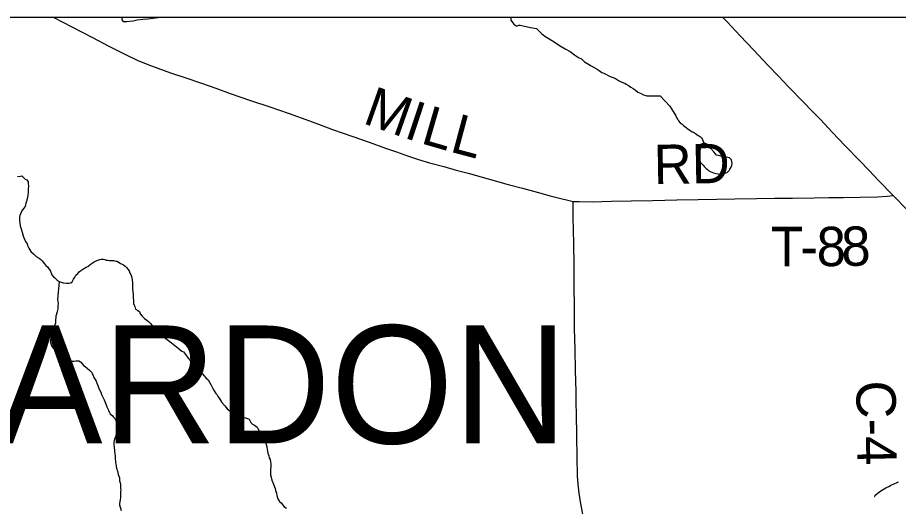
# Model space of a CAD drawing. Extents: x 103424 to 286016, y 38711 to 110967.
# Drawn here: x 127210 to 133964, y 107218 to 110967 of the extents above; entities that cross this region are included whole.
import ezdxf

# ---------------------------------------------------------------- set-up
doc = ezdxf.new("R2010")
doc.units = 0
for name, color, linetype in [('GM_X_Corporation', 7, 'Continuous'), ('GM_X_County_Road', 7, 'Continuous'), ('GM_X_County_Road_Text', 7, 'Continuous'), ('GM_X_Minor_Lake', 7, 'Continuous'), ('GM_X_Minor_River', 7, 'Continuous'), ('GM_X_Township_Road', 7, 'Continuous'), ('GM_X_Township_Road_Text', 7, 'Continuous'), ('GM_X_Township_Text', 7, 'Continuous')]:
    doc.layers.add(name, color=color, linetype=linetype)

msp = doc.modelspace()

# ---------------------------------------------------------------- linework, layer by layer
at = {"layer": 'GM_X_Corporation'}
msp.add_lwpolyline([(103423.7, 96534.8), (103423.7, 38711.2), (175679.7, 38711.2), (175679.7, 110967.2), (119699, 110967.2), (119716.9, 106542.5), (119719.8, 106322.8), (119720.8, 106006.3), (119709.7, 99445.7), (119706.4, 99064.2), (119663.9, 96690), (117026.4, 96688.2), (115542.1, 96665), (105081.7, 96574.5)], close=True, dxfattribs=at)
msp.add_lwpolyline([(148354.5, 110967.2), (119699, 110967.2), (119716.9, 106542.5), (119719.8, 106322.8), (119720.8, 106006.3), (119709.7, 99445.7), (119706.4, 99064.2), (119663.9, 96690), (127752.9, 96778.3), (127904.6, 96781), (127960.9, 96782.1), (128017.2, 96783.1), (128144.7, 96785.8), (131350.5, 96844.5), (131500.4, 96848.9), (132289.6, 96863.9), (132581, 96869.6), (132838, 96874.6), (133225.9, 96882.3), (133496.3, 96888.5), (133864.7, 96896.9), (134160.1, 96903.7)], dxfattribs=at)
at = {"layer": 'GM_X_County_Road'}
msp.add_lwpolyline([(132619.3, 110967.2), (132651.2, 110934.2), (132752, 110826.7), (132852.9, 110719.3), (132967, 110600), (133044.9, 110518.6), (133122.8, 110437.2), (133237.5, 110318.4), (133301.8, 110251.8), (133366.1, 110185.1), (133460.2, 110086.2), (133554.3, 109987.3), (133668.4, 109868), (133740.1, 109793.2), (133811.7, 109718.3), (133925, 109602.4), (134033.5, 109490.7), (134125.5, 109396)], dxfattribs=at)
at = {"layer": 'GM_X_Minor_Lake'}
msp.add_line((128248.7, 110963), (128288.1, 110967.2), dxfattribs=at)
for points in [[(128010.2, 110967.2), (128010.3, 110960.8), (128010.4, 110950.7), (128020.6, 110938.6), (128046.9, 110936.9), (128069.1, 110939.1), (128095.3, 110941.4), (128127.5, 110949.8), (128171.9, 110954.3), (128208.2, 110958.7), (128248.7, 110963)], [(132448, 109993.7), (132444.5, 109959.3), (132440.7, 109945.1), (132439, 109932.9), (132437.2, 109920.8), (132437.4, 109908.6), (132435.6, 109892.5), (132435.9, 109876.3), (132442.3, 109860.3), (132456.7, 109844.3), (132467, 109834.4), (132475.2, 109824.5), (132489.6, 109810.6), (132499.8, 109802.7), (132510.1, 109792.8), (132522.3, 109787), (132534.5, 109781.1), (132546.7, 109777.3), (132567, 109771.6), (132583.2, 109767.8), (132593.3, 109766), (132605.4, 109766.2), (132623.5, 109768.6), (132633.5, 109772.8), (132651.6, 109779.2), (132665.5, 109793.6), (132671.3, 109803.8), (132681.1, 109820.1), (132686.9, 109836.4), (132688.7, 109846.5), (132688.4, 109862.7), (132684.1, 109876.7), (132669.7, 109892.6), (132655.6, 109894.4), (132643.4, 109896.2), (132627.3, 109897.9), (132617.1, 109899.8), (132602.9, 109905.6), (132584.7, 109909.3), (132570.5, 109913.1), (132562.2, 109923), (132547.9, 109936.9), (132527.2, 109962.8), (132516.9, 109974.7), (132508.6, 109984.7), (132498.4, 109996.6), (132486.2, 110000.4), (132476.1, 110002.3), (132466, 110002.1), (132454, 109995.8), (132448, 109993.7)], [(132448, 109993.7), (132444.5, 109959.3), (132440.7, 109945.1), (132439, 109932.9), (132437.2, 109920.8), (132437.4, 109908.6), (132435.6, 109892.5), (132435.9, 109876.3), (132442.3, 109860.3), (132456.7, 109844.3), (132467, 109834.4), (132475.2, 109824.5), (132489.6, 109810.6), (132499.8, 109802.7), (132510.1, 109792.8), (132522.3, 109787), (132534.5, 109781.1), (132546.7, 109777.3), (132567, 109771.6), (132583.2, 109767.8), (132593.3, 109766), (132605.4, 109766.2), (132623.5, 109768.6), (132633.5, 109772.8), (132651.6, 109779.2), (132665.5, 109793.6)], [(132665.5, 109793.6), (132671.3, 109803.8), (132681.1, 109820.1), (132686.9, 109836.4), (132688.7, 109846.5), (132688.4, 109862.7), (132684.1, 109876.7), (132669.7, 109892.6), (132655.6, 109894.4), (132643.4, 109896.2), (132627.3, 109897.9), (132617.1, 109899.8), (132602.9, 109905.6), (132584.7, 109909.3), (132570.5, 109913.1), (132562.2, 109923), (132547.9, 109936.9), (132527.2, 109962.8), (132516.9, 109974.7), (132508.6, 109984.7), (132498.4, 109996.6), (132486.2, 110000.4), (132476.1, 110002.3), (132466, 110002.1), (132454, 109995.8), (132448, 109993.7)]]:
    msp.add_lwpolyline(points, dxfattribs=at)
at = {"layer": 'GM_X_Minor_River'}
for points in [[(130990, 110967.2), (130991.5, 110964.3), (130993.7, 110948.1), (131014.3, 110918), (131034.6, 110904.1), (131044.7, 110904.2), (131054.8, 110908.3), (131064.9, 110908.4), (131143.8, 110891), (131174.2, 110887.3), (131190.4, 110883.4), (131202.6, 110871.4), (131212.9, 110859.4), (131227.2, 110845.4), (131253.7, 110825.5), (131278.1, 110809.6), (131300.4, 110797.7), (131324.9, 110781.8), (131351.3, 110763.8), (131377.8, 110745.9), (131410.3, 110728.1), (131446.9, 110706.2), (131481.6, 110682.3), (131512.1, 110662.4), (131534.4, 110650.5), (131556.9, 110628.5), (131587.4, 110610.7), (131609.8, 110596.8), (131632.2, 110584.9), (131654.5, 110570.9), (131670.8, 110561), (131681, 110553), (131691.2, 110547.1), (131705.4, 110541.1), (131721.6, 110533.2), (131737.9, 110523.3), (131754.2, 110515.4), (131776.5, 110507.5), (131794.7, 110499.6), (131819.1, 110485.7), (131839.5, 110473.8), (131855.7, 110467.9), (131865.8, 110464), (131878, 110456), (131894.3, 110446.1), (131912.6, 110434.2), (131931, 110422.2), (131947.2, 110412.3), (131965.6, 110396.3), (131992, 110384.4), (132010.3, 110374.5), (132026.5, 110370.7), (132036.6, 110366.7), (132138.2, 110365.9)], [(132138.2, 110365.9), (132212.6, 110288.4), (132225.1, 110268.4), (132258.3, 110214.5), (132266.7, 110196.5), (132273, 110184.4), (132279.2, 110174.5), (132291.6, 110160.5), (132305.9, 110148.7), (132316.2, 110140.8), (132326.4, 110132.9), (132336.7, 110123), (132348.9, 110115.1), (132359.2, 110105.2), (132373.4, 110099.4), (132383.6, 110091.5), (132393.8, 110087.6), (132408.1, 110077.8), (132418.3, 110069.9), (132428.5, 110064), (132438.7, 110058.1), (132455.1, 110046.3), (132476.1, 110002.3)], [(127210.4, 109748.9), (127232.5, 109751.2), (127242.6, 109753.3), (127267.2, 109727.3), (127281.3, 109723.4), (127291.6, 109707.3), (127291.7, 109697.2), (127294.1, 109671), (127292.2, 109656.8), (127292.4, 109640.7), (127290.5, 109626.5), (127288.8, 109606.3), (127285, 109586.1), (127281.1, 109569.9), (127279.2, 109557.7), (127273.3, 109543.5), (127267.5, 109519.2), (127255.6, 109503), (127241.7, 109484.6), (127228, 109450.2), (127226.1, 109436), (127224.2, 109423.9), (127224.4, 109409.7), (127226.6, 109393.6), (127230.9, 109369.4), (127237.2, 109347.2), (127245.6, 109321.1), (127254, 109292.9), (127264.4, 109264.7), (127274.8, 109242.6), (127283, 109232.6), (127287.2, 109218.5), (127297.5, 109198.4), (127312, 109174.3), (127332.4, 109154.3), (127352.8, 109134.3), (127375.2, 109122.4), (127389.4, 109112.4), (127401.7, 109098.4), (127414, 109080.4), (127426.3, 109066.3), (127438.6, 109054.3), (127463.2, 109022.3), (127473.6, 108994.1), (127485.9, 108978.1), (127496.1, 108970.1), (127512.5, 108954.1), (127528.8, 108942.1), (127545, 108938.2), (127559.2, 108932.3), (127585.4, 108930.6), (127603.6, 108930.8), (127617.7, 108932.9), (127627.7, 108941.1), (127639.6, 108961.4), (127649.6, 108975.7), (127657.4, 108991.9)], [(127657.4, 108991.9), (127671.4, 109004.2), (127683.4, 109016.4), (127695.4, 109026.6), (127709.4, 109036.9), (127723.5, 109045.1), (127735.5, 109053.3), (127749.6, 109057.5), (127767.6, 109073.8), (127781.6, 109084), (127797.6, 109094.3), (127817.7, 109104.6), (127839.9, 109110.9), (127849.9, 109113), (127868.1, 109113.2), (127880.3, 109111.3), (127890.4, 109107.3), (127902.5, 109105.4), (127914.7, 109103.5), (127928.8, 109103.7), (127945, 109103.8), (127963.2, 109100), (127973.3, 109098.1), (127999.8, 109080.1), (128012, 109076.2), (128022.1, 109070.3), (128034.4, 109060.3), (128044.6, 109050.3), (128054.8, 109038.3), (128065.1, 109024.2), (128071.3, 109008.1), (128079.5, 108996.1), (128083.7, 108982), (128088.1, 108955.8), (128090.4, 108933.6), (128090.6, 108915.4), (128090.9, 108887.1), (128093.2, 108862.9), (128095.4, 108844.8), (128097.6, 108830.7), (128097.8, 108818.5), (128098, 108798.3), (128100.3, 108774.1), (128104.5, 108762), (128108.6, 108752), (128114.9, 108731.9), (128133.2, 108719.9), (128145.4, 108714), (128149.7, 108695.8), (128166.1, 108675.8), (128184.4, 108659.8), (128200.8, 108645.8), (128215, 108635.9), (128227.3, 108623.9), (128241.6, 108605.9), (128258, 108581.8), (128280.5, 108557.8), (128311.1, 108531.8), (128345.8, 108505.9), (128378.4, 108482), (128453.8, 108422.2), (128470.1, 108408.2), (128482.3, 108402.2), (128504.9, 108372.2), (128529.5, 108342.1), (128558.1, 108308.1), (128586.8, 108274), (128607.3, 108254), (128619.5, 108244), (128627.7, 108234), (128637.9, 108222), (128656.3, 108202), (128670.6, 108188), (128680.9, 108171.9), (128693.3, 108151.9), (128703.6, 108127.7), (128718.1, 108103.6), (128730.4, 108083.6), (128740.6, 108073.6), (128748.9, 108059.5), (128761.2, 108041.4), (128777.7, 108015.3), (128798.2, 107989.3), (128818.6, 107965.3), (128839, 107951.3), (128857.3, 107943.4), (128877.6, 107929.5), (128902.1, 107911.6), (128926.4, 107899.7), (128956.8, 107895.9), (128973, 107892.1), (128985.2, 107888.1), (128999.6, 107862), (129011.9, 107848), (129026.1, 107840.1), (129038.3, 107834.1), (129048.5, 107826.2), (129052.7, 107816.1), (129065, 107792), (129087.5, 107770), (129101.9, 107747.9)], [(127528.8, 108942.1), (127516.2, 108804.7), (127520.6, 108774.4), (127518.8, 108754.2), (127518.9, 108744.1), (127519, 108734), (127515.1, 108721.8), (127513.3, 108709.7), (127503.5, 108677.3), (127503.7, 108663.1), (127501.8, 108651), (127500, 108638.9), (127500.1, 108622.7), (127494.3, 108604.5), (127486.5, 108576.1), (127480.8, 108551.8), (127472.9, 108529.5), (127465.1, 108511.3), (127463.2, 108497.1), (127461.3, 108485), (127463.5, 108474.9), (127467.7, 108460.8), (127469.8, 108450.7), (127482.1, 108432.7), (127498.5, 108416.7), (127506.7, 108406.6), (127521, 108388.6), (127531.3, 108376.6), (127543.5, 108364.6), (127553.7, 108356.6), (127563.9, 108350.7), (127574.1, 108344.7), (127588.3, 108338.8), (127606.5, 108332.9), (127616.6, 108331), (127628.8, 108331.1), (127640.9, 108331.2), (127657, 108335.4), (127669.1, 108335.5), (127679.2, 108333.6), (127691.4, 108325.7), (127707.8, 108309.7), (127716, 108299.7), (127728.2, 108289.7), (127764.9, 108259.7), (127779.2, 108245.8), (127783.4, 108235.7), (127789.6, 108221.6), (127795.8, 108205.5), (127804.1, 108191.5), (127812.3, 108177.4), (127818.5, 108163.3), (127824.8, 108145.2), (127831.1, 108129.1), (127839.3, 108111), (127847.6, 108094.9), (127853.9, 108076.8), (127862.2, 108060.7), (127868.4, 108046.7), (127874.6, 108034.6), (127878.8, 108022.5), (127885, 108008.5), (127889.2, 107996.4), (127895.4, 107980.3), (127903.7, 107962.2), (127907.9, 107952.1), (127912, 107942.1), (127920.3, 107928), (127934.5, 107916), (127946.8, 107902), (127957, 107892), (127963.2, 107877.9), (127967.5, 107861.8), (127971.7, 107843.7), (127973.9, 107827.6), (127974.1, 107813.4), (127972.3, 107797.2), (127962.6, 107760.8), (127960.7, 107750.7), (127956.8, 107740.5), (127950.9, 107724.3), (127949, 107714.2), (127949.2, 107700.1), (127949.3, 107687.9), (127951.4, 107677.9), (127951.6, 107667.8), (127953.8, 107649.6), (127953.9, 107639.5), (127956.1, 107621.4), (127958.3, 107605.2), (127958.6, 107579), (127960.8, 107564.8), (127961, 107552.7), (127963.1, 107540.6), (127967.3, 107530.6), (127967.4, 107520.5), (127971.6, 107504.3), (127973.8, 107494.3), (127977.9, 107484.2), (127980.1, 107474.1), (127982.2, 107462)], [(129101.9, 107747.9), (129120.9, 107675.4), (129123.2, 107653.2), (129129.6, 107625), (129135.9, 107604.8), (129140.1, 107590.7), (129146.3, 107576.7), (129150.6, 107558.5), (129152.8, 107544.4), (129153, 107524.2), (129149.3, 107495.9), (129149.4, 107485.8), (129149.5, 107473.7), (129149.7, 107459.6), (129154, 107441.4), (129160.3, 107419.3), (129172.7, 107389.1), (129185.3, 107354.9), (129191.6, 107330.7), (129195.7, 107320.6), (129198, 107302.5), (129206.4, 107276.3), (129214.6, 107264.3), (129218.7, 107254.2), (129233, 107242.2), (129251.5, 107218.2), (129271.8, 107204.2)], [(127982.2, 107462), (127986.4, 107450), (127990.6, 107437.9), (127992.8, 107423.8), (127992.9, 107413.7), (127997.1, 107397.5), (127999.3, 107385.5), (127999.4, 107375.4), (127999.6, 107355.2), (128001.8, 107345.1), (127999.9, 107332.9), (128000.1, 107316.8), (127998.2, 107300.6), (127998.4, 107286.5), (127996.6, 107270.3), (127994.8, 107252.1), (127992.9, 107240), (127993, 107229.9), (128005.6, 107187.6)], [(133781.9, 107292.7), (133783.9, 107292.7), (133785.7, 107304.9), (133829.5, 107336), (133867.4, 107360.9), (133895.4, 107373.5), (133905.4, 107379.7), (133931.5, 107390.3), (133955.5, 107400.8), (133965.5, 107405.1)]]:
    msp.add_lwpolyline(points, dxfattribs=at)
at = {"layer": 'GM_X_Township_Road'}
for points in [[(127487.7, 110967.2), (127626.3, 110895.5), (127705.5, 110854.6), (127784.7, 110813.6), (127910.8, 110748.5), (128037, 110683.3), (128127.3, 110640.7), (128209.3, 110607.3), (128284.6, 110579.1), (128382.6, 110544.8), (128501, 110504.3), (128619.3, 110463.8), (128729.9, 110424.9), (128840.6, 110386), (128996.7, 110332.4), (129145, 110281.5), (129293.4, 110230.6), (129448.6, 110174.4), (129537.4, 110142.2), (129626.2, 110110), (129781.8, 110054.9), (129906.5, 110010.7), (130031.1, 109966.6), (130115.3, 109937.1), (130199.4, 109907.6), (130285.1, 109879.3), (130369.8, 109853.9), (130478.5, 109823.8), (130572.2, 109798.2), (130665.9, 109772.7), (130819.5, 109730.4), (130973.1, 109688.2), (131083.2, 109658), (131193.2, 109627.9), (131294.1, 109601), (131376, 109579.4), (131428.4, 109567), (131470.3, 109557.8), (131516.9, 109556.5), (131615.8, 109555.2), (131765.2, 109558.5), (131914.5, 109561.7), (132079.5, 109565.4), (132172.2, 109567.5), (132265, 109569.6), (132430, 109572), (132570.6, 109574.1), (132711.1, 109576.1), (132876.1, 109578.8), (133014.7, 109581.1), (133153.3, 109583.3), (133318.3, 109585.3), (133430.1, 109586.6), (133541.8, 109587.9), (133672.5, 109590.5), (133803.1, 109593.2), (133877.9, 109596.4), (133925, 109602.4)], [(131545.7, 107157.2), (131526.8, 107253.3), (131517, 107320), (131509.2, 107387.3), (131505, 107452.5), (131500.8, 107594.2), (131498, 107759.2), (131495.3, 107924.3), (131493.8, 108011), (131492.4, 108097.8), (131488.7, 108262.8), (131485.1, 108422.2), (131481.5, 108581.7), (131480.4, 108746.8), (131479.4, 108907.6), (131478.4, 109068.4), (131475.4, 109233.5), (131473.5, 109336.4), (131471.7, 109439.4), (131470.3, 109557.8)]]:
    msp.add_lwpolyline(points, dxfattribs=at)

# ---------------------------------------------------------------- texts
at = {"layer": 'GM_X_County_Road_Text'}
msp.add_text('C-4', height=301.87, rotation=270.91791, dxfattribs=at).set_placement((133640.3, 108181.3))
at = {"layer": 'GM_X_Township_Road_Text'}
for s, height, rotation, p in [('M', 301.9, 340.5385, (129848.8, 110159.8)), ('I', 301.9, 341.63827, (130163.6, 110048.6)), ('L', 301.9, 343.83147, (130293.1, 110005.9)), ('L', 301.9, 345.06227, (130516.7, 109941.2)), ('RD', 301.87, 0.9875, (132090.2, 109689.7)), ('T', 301.9, 0.00429, (132987, 109060.4)), ('8', 301.9, 0.21257, (133338, 109060.5)), ('8', 301.9, 1.10241, (133529.1, 109061.3)), ('-', 301.9, 0.04281, (133213, 109060.4))]:
    msp.add_text(s, height=height, rotation=rotation, dxfattribs=at).set_placement(p)
at = {"layer": 'GM_X_Township_Text'}
msp.add_text('CHARDON', height=905.61, rotation=0.00001, dxfattribs=at).set_placement((125305.3, 107700.3))

doc.saveas('drawing.dxf')
